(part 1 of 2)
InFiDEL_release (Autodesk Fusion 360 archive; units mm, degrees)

design "assAll" references "filaSens"
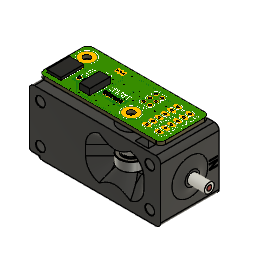
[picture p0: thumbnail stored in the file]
base_feature "Base Feature1"
base_feature "Base Feature1"
base_feature "Base Feature1"
base_feature "Base Feature1"
base_feature "Base Feature1"
base_feature "Base Feature1"
revolve "Revolve1" sketch "unnamed" AlongAngle 360
sketch "MainSketch" plane through (0, 0, 0) normal (0, 0, 1) x axis (1, 0, 0)
  line L1 (33.1, 16.4) -> (33.1, 4.8)
  line L2 (20.6, 11.4) -> (45.6, 11.4)
  line L3 (20.6, 9.8) -> (20.6, 11.4)
  line L4 (45.6, 9.8) -> (20.6, 9.8)
  line L5 (45.6, 11.4) -> (45.6, 9.8)
  line L6 (20.6, 9.8) -> (45.6, 11.4)
  line L7 (45.6, 9.8) -> (20.6, 11.4)
  line L8 (-2, -2) -> (-2, 22)
  line L9 (-2, 10.8604) -> (-2, -2)
  line L10 (-2, 19.7396) -> (-2, 10.8604)
  line L11 (-2, 22) -> (-2, 19.7396)
  line L12 (-2, 9.8969) -> (-2, 10.0463)
  line L13 (-2, 14.9334) -> (-2, 5.472)
  line L14 (52, -2) -> (52, 22)
  line L15 (52, 22) -> (52, -2)
  line L16 (52, 16.8544) -> (52, 14.8608)
  line L17 (52, 14.8608) -> (52, 16.8544)
  line L18 (52, 18.509) -> (52, 18.7911)
  line L19 (52, 17.416) -> (52, 18.509)
  line L20 (52, 16.3266) -> (52, 17.416)
  line L21 (52, 15.8861) -> (52, 16.3266)
  line L22 (52, 16.1522) -> (52, 15.8861)
  line L23 (52, 16.7975) -> (52, 16.1522)
  line L24 (52, 16.3987) -> (52, 16.7975)
  line L25 (52, 16.6738) -> (52, 16.3987)
  line L26 (52, 17.4116) -> (52, 16.6738)
  line L27 (52, 18.0675) -> (52, 17.4116)
  line L28 (52, 18.2785) -> (52, 18.0675)
  line L29 (52, 18.1646) -> (52, 18.2785)
  line L30 (52, 20.5) -> (52, 18.1646)
  line L31 (52, 19.9873) -> (52, 20.5)
  line L32 (52, 18.7671) -> (52, 19.9873)
  line L33 (52, 18.7911) -> (52, 18.7671)
  line L34 (52, -0.5) -> (52, 4.5)
  line L35 (52, 3.9729) -> (52, -0.5)
  line L36 (52, -0.5) -> (52, 3.9729)
  line L37 (52, 4.5) -> (52, -0.5)
  line L38 (52, 0.4167) -> (52, 4.5)
  line L39 (52, 4.5) -> (52, 0.4167)
  line L40 (52, -0.5) -> (52, 0.0063)
  line L41 (52, 0.0063) -> (52, -0.5)
  line L42 (52, 3.9937) -> (52, 0.0063)
  line L43 (52, 4.5) -> (52, 3.9937)
  line L44 (52, 3.9937) -> (52, 4.5)
  line L45 (52, 0.0063) -> (52, 3.9937)
  line L46 (52, 19.8165) -> (52, 20.5)
  line L47 (52, 16) -> (52, 19.8165)
  line L48 (52, 19.9873) -> (52, 16)
  line L49 (52, 20.5) -> (52, 19.9873)
  line L50 (52, 16) -> (52, 16.4557)
  line L51 (52, 16.4557) -> (52, 16)
  line L52 (52, 19.4747) -> (52, 16.4557)
  line L53 (52, 19.8734) -> (52, 19.4747)
  line L54 (52, 19.9971) -> (52, 19.8734)
  line L55 (52, 20.5) -> (52, 19.9971)
  line L56 (52, 16.4557) -> (52, 20.5)
  line L57 (52, 13.4092) -> (52, 7.0169)
  line L58 (52, 10.1345) -> (52, 7.0169)
  line L59 (20.6, 10.6) -> (45.6, 10.6)
  line L60 (-10, 8.5396) -> (-2, 8.5396)
  line L61 (60, 10.0041) -> (52, 10.0041)
  circle C1 centre (33.1, 16.4) radius 1.45
  circle C2 centre (33.1, 16.4) radius 5
  circle C3 centre (33.1, 4.8) radius 5
  circle C4 centre (33.103, 16) radius 1.4
  arc A1 centre (-2, 158.5396) radius 150 clockwise from (15.5501, 9.5698) to (-2, 8.5396)
  arc A2 centre (33.1, -139.4) radius 150 clockwise from (-2, 6.4355) to (15.5501, 9.5698)
  arc A3 centre (52, 160.0041) radius 150 clockwise from (52, 10.0041) to (42.55, 10.302)
  arc A4 centre (33.1, -139.4) radius 150 clockwise from (45.6, 10.0783) to (52, 9.4045)
  arc A5 centre (33.1, -139.4) radius 150 clockwise from (15.5501, 9.5698) to (42.55, 10.302)
  arc A6 centre (33.1, -139.4) radius 150 clockwise from (42.55, 10.302) to (45.6, 10.0783)
  point P2 (33.1, 4.8)
  point P3 (33.1, 4.8)
  point P4 (33.1, 16.4)
  point P5 (33.1, 16.4)
  point P6 (33.1, 16.4)
  point P11 (33.1, 10.6)
  point P14 (52, 9.4045)
  point P15 (-2, 6.4355)
  point P60 (45.6, 10.6)
  point P61 (20.6, 10.6)
  point P63 (-2, 8.5396)
  point P68 (52, 10.0041)
  point P67 (42.55, 10.302)
  point P71 (45.6, 10.0783)
  point P8 (20.6, 11.4)
  point P9 (20.6, 9.8)
  point P10 (45.6, 9.8)
  point P65 (-10, 8.5396)
  point P70 (60, 10.0041)
  coincident P2 P3
  vertical L1
  coincident P4 P5
  coincident P4 P6
  horizontal L2
  perpendicular L2 L3
  parallel L2 L4
  parallel L3 L5
  coincident L6 P11
  coincident L7 P11
  coincident L1 P11
  tangent C2 L2
  tangent L4 C3
  coincident P11 A4
  coincident P14 L14
  coincident P15 L13
  midpoint L5 P60
  midpoint L3 P61
  tangent L59 A4
  tangent A1 A4
  coincident L8 P63
  horizontal L60
  tangent A1 L60
  concentric A2 A4
  tangent A3 A4
  coincident L15 P68
  coincident P67 A4
  perpendicular L15 L61
  tangent A3 L61
  coincident L5 P71
  concentric A4 A5
  concentric A4 A6
  dimension "d29" diameter C2 = 10
  dimension "d30" distance P8 P9 = 1.6 (= "RollerCenter")
  dimension "d31" distance P9 P10 = 25
  dimension "d52" radius A4 = 150 (= "TensionArc")
  dimension "d54" radius A1 = 150 (= "TensionArc")
  dimension "d79" radius A3 = 150 (= "TensionArc")
  dimension "d80" distance P63 P65 = 8
  dimension "d81" distance P68 P70 = 8
  dimension "d318" diameter C1 = 2.9 (= "PinPressDia")
work_plane "WorkPlane1" AlongDistance 16.4
sketch "Sketch1" plane through (0, 16.4, 0) normal (0, 1, 0) x axis (1, 0, 0)
  line L1 (33.103, 13) -> (33.103, 0)
  line L2 (30.603, -2) -> (35.603, -2)
  line L3 (24.603, -8) -> (30.603, -2)
  line L4 (47.35, -8) -> (32.35, -8)
  line L5 (33.103, -8) -> (24.603, -8)
  line L6 (33.103, -8) -> (33.103, 0)
  line L7 (29.603, -3) -> (29.603, -8)
  point P2 (33.103, 0)
  point P3 (33.103, 0)
  point P6 (30.603, -2)
  point P7 (30.603, -2)
  point P11 (33.103, -8)
  point P12 (33.103, -8)
  point P13 (29.603, -8)
  point P14 (29.603, -3)
  coincident P2 P3
  vertical L1
  coincident P6 P7
  coincident L4 P11
  coincident L4 P12
  perpendicular L4 L6
  coincident P11 P12
  horizontal L5
  coincident L5 P13
  coincident L3 P14
  perpendicular L5 L7
  dimension "d2" angle L2 L3 = 135
  dimension "d3" distance P7 L7 = 1
revolve "Revolve2" sketch "Sketch1" AlongAngle 360
extrude "Extrude2" sketch "unnamed" blind 17
extrude "Extrude3" cut sketch "MainSketch" profile of C1 C4 along normal blind 21.8
sketch "Sketch2" plane through (0, 0, 0) normal (0, 0, -1) x axis (1, 0, 0)
  arc A1 centre (39.85, -15.8) radius 7.5 clockwise from (32.3789, -15.142) to (32.6121, -17.7655)
  circle C1 centre (39.85, -15.8) radius 3
  circle C2 centre (33.1, -16.4) radius 6
  arc A2 centre (33.1, -16.4) radius 1.45 clockwise from (32.3789, -15.142) to (32.6121, -17.7655)
  point P5 (33.1, -16.4)
  point P6 (33.1, -16.4)
  coincident P5 P6
  dimension "d13" diameter C2 = 12
sketch "Sketch3" plane through (0, 0, 0) normal (0, 0, 1) x axis (1, 0, 0)
  line L1 (14.76, 16.21) -> (18.26, 16.21)
  line L2 (16.51, 21.21) -> (16.51, 16.21)
  line L3 (16.51, 23.21) -> (16.51, 21.21)
  line L4 (20.01, 23.21) -> (16.51, 23.21)
  line L5 (20.01, 21.21) -> (20.01, 23.21)
  line L6 (16.51, 21.21) -> (20.01, 21.21)
  line L7 (11.01, 24.7652) -> (40.2281, 23.2905)
  line L8 (11.01, 24.21) -> (22.01, 24.21)
  line L9 (11.01, 20.21) -> (11.01, 24.21)
  line L10 (22.01, 20.21) -> (11.01, 20.21)
  line L11 (22.01, 24.21) -> (22.01, 20.21)
  line L12 (11.01, 20.21) -> (22.01, 24.21)
  line L13 (22.01, 20.21) -> (11.01, 24.21)
  line L14 (13.01, 23.21) -> (16.51, 23.21)
  line L15 (13.01, 21.21) -> (13.01, 23.21)
  line L16 (16.51, 21.21) -> (13.01, 21.21)
  line L17 (16.51, 23.21) -> (16.51, 21.21)
  line L18 (11.01, 24.21) -> (11.01, 24.7652)
  line L19 (22.01, 21.21) -> (20.01, 21.21)
  line L20 (11.01, 21.21) -> (13.01, 21.21)
  line L21 (34.0875, 20.6004) -> (22.01, 21.21)
  line L22 (43.3307, 23.1339) -> (40.2281, 23.2905)
  line L23 (45.4139, 20.8292) -> (43.3307, 23.1339)
  arc A1 centre (39.85, 15.8) radius 7.5 clockwise from (32.6121, 17.7655) to (32.3789, 15.142)
  arc A2 centre (39.85, 15.8) radius 7.5 clockwise from (32.5804, 13.9552) to (32.3789, 15.142)
  arc A3 centre (39.85, 15.8) radius 7.5 clockwise from (32.6121, 17.7655) to (33.02, 18.8986)
  point P4 (16.51, 16.21)
  point P12 (40.2281, 23.2905)
  point P18 (16.51, 22.21)
  point P14 (22.01, 24.21)
  point P21 (22.01, 21.21)
  point P22 (11.01, 21.21)
  point P26 (45.4139, 20.8292)
  point P5 (16.51, 21.21)
  point P6 (16.51, 23.21)
  point P7 (20.01, 23.21)
  midpoint L1 P4
  perpendicular L1 L2
  parallel L2 L3
  perpendicular L3 L4
  perpendicular L4 L5
  horizontal L6
  coincident A1 P12
  tangent A1 L7
  horizontal L8
  perpendicular L8 L9
  parallel L8 L10
  parallel L9 L11
  coincident L12 P18
  coincident L13 P18
  midpoint L3 P18
  horizontal L14
  vertical L15
  horizontal L16
  vertical L17
  equal L4 L14
  vertical L18
  coincident L7 P14
  coincident L11 P21
  perpendicular L11 L19
  coincident L9 P22
  perpendicular L9 L20
  parallel L7 L21
  tangent A1 L22
  coincident A1 P26
  tangent A1 L23
  dimension "d16" distance P4 P5 = 5
  dimension "d17" distance P5 P6 = 2
  dimension "d18" distance P6 P7 = 3.5
  dimension "d19" distance L5 L11 = 2
  dimension "d20" distance L4 L8 = 1
  dimension "d24" angle L22 L23 = 135
extrude "Extrude5" add sketch "Sketch3" profile of L3 L4 L5 L6 A1 L7 L8 L9 L11 L14 L15 L16 L17 L18 L19 L20 L21 L22 L23 to an object User Parameter 5 named "MagnetOffset" User Parameter 5 named "Pretension" User Parameter 1.6 named "RollerCenter" User Parameter 150 named "TensionArc" User Parameter 2.9 named "PinPressDia" User Parameter 4.15 named "PTFEclear" User Parameter 3.7 named "M3InsertDia" User Parameter 1.4 named "Roller_Center_dyn"
revolve "Revolve3" sketch "Sketch3" AlongAngle 360
sketch "Sketch5" plane through (0, 0, 8) normal (0, 0, 1) x axis (-1, 0, 0)
  line L1 (-43.3307, -23.1339) -> (-45.4139, -20.8292)
  line L2 (-40.2281, -23.2905) -> (-43.3307, -23.1339)
  line L3 (-11.01, -24.7652) -> (-40.2281, -23.2905)
  line L4 (-11.01, -21.21) -> (-11.01, -24.7652)
  line L5 (-22.01, -21.21) -> (-11.01, -21.21)
  line L6 (-34.0875, -20.6004) -> (-22.01, -21.21)
  line L7 (-13.01, -21.21) -> (-20.01, -21.21)
  line L8 (-16.51, -21.21) -> (-33.103, -16.4)
  circle C1 centre (-33.1, -16.4) radius 1.45
  circle C2 centre (-39.85, -15.8) radius 5
  arc A1 centre (-39.85, -15.8) radius 7.5 clockwise from (-45.4139, -20.8292) to (-32.9316, -12.9042)
  arc A2 centre (-39.85, -15.8) radius 7.5 clockwise from (-33.5512, -19.8712) to (-34.0875, -20.6004)
  arc A3 centre (-33.103, -16.4) radius 3.5 clockwise from (-32.9316, -12.9042) to (-33.5512, -19.8712)
  point P13 (-33.103, -16.4)
  point P16 (-33.103, -16.4)
  coincident P13 P16
extrude "Extrude6" add sketch "Sketch5" profile of L5 L6 A2 A3 L7 L8 against normal blind 5
extrude "Extrude7" cut of existing geometry blind -1.4
fillet "Fillet1" radius 2
sketch "Sketch6" plane through (1.2748, 25.2566, 0) normal (0.0504, 0.9987, 0) x axis (-0.9987, 0.0504, 0)
  line L1 (-39.0029, 8) -> (-9.7476, 8)
  line L2 (-39.0029, 0) -> (-39.0029, 8)
  line L3 (-9.7476, 0) -> (-39.0029, 0)
  line L4 (-9.7476, 8) -> (-9.7476, 0)
  line L5 (-14.3324, 5.4833) -> (-28.319, 8)
  circle C1 centre (-15.319, 0) radius 5.5714
  closed curve K1 centre (-15.319, 0)
  point P5 (-9.7476, 0)
  point P10 (-28.319, 8)
  point P11 (-14.3324, 5.4833)
  point P6 (-15.319, 0)
  concentric C1 K1
  coincident P5 C1
  coincident L1 P10
  coincident C1 P11
  tangent C1 L5
  dimension "d39" distance P6 P10 = 13
extrude "Extrude8" cut sketch "Sketch6" profile of L1 L4 C1 L5 against normal blind 14
fillet "Fillet2" radius 20
fillet "Fillet3" radius 5
extrude "Extrude9" cut sketch "Sketch2" to an object
fillet "Fillet4" radius 5
split "Split1" bodies "LeverPlastic"
sketch "Sketch7" plane through (0, 16.4, 0) normal (0, 1, 0) x axis (1, 0, 0)
  line L1 (31.65, -8) -> (31.65, -2)
  line L2 (29.603, -8) -> (31.65, -8)
  line L3 (29.603, -7.9999) -> (29.603, -8)
  line L4 (29.1901, -3) -> (29.1901, -7.9807)
  line L5 (29.603, -3) -> (29.1901, -3)
  line L6 (30.603, -2) -> (29.603, -3)
  line L7 (31.65, -2) -> (30.603, -2)
  line L8 (26.5009, -3) -> (29.1901, -3)
  line L9 (27.1, -3) -> (29.1901, -3)
  line L10 (27.1, 2.2) -> (27.1, -3)
  line L11 (33.1, 2.2) -> (27.1, 2.2)
  line L12 (33.8821, -2) -> (33.02, -2)
  line L13 (33.1, -2) -> (33.1, 2.2)
  line L14 (33.1, -2) -> (31.65, -2)
  line L15 (34.55, -8) -> (31.65, -8)
  line L16 (34.55, -8) -> (34.55, -2)
  line L17 (33.1, 3.5) -> (33.1, -8)
  closed curve K1 centre (29.6296, -3)
  point P8 (29.1901, -3)
  point P13 (29.1901, -3)
  point P19 (33.1, -2)
  point P2 (31.65, -2)
  point P20 (31.65, -2)
  point P3 (31.65, -8)
  point P21 (31.65, -8)
  point P22 (34.55, -8)
  point P25 (33.1, -8)
  point P15 (27.1, 2.2)
  point P16 (33.1, 2.2)
  coincident P8 P13
  parallel L5 L9
  perpendicular L5 L10
  perpendicular L10 L11
  coincident L12 P19
  perpendicular L11 L13
  coincident P2 P20
  coincident P3 P21
  perpendicular L1 L15
  coincident P22 L16
  midpoint L15 P25
  perpendicular L15 L17
  collinear L13 L17
  dimension "d50" distance P15 P16 = 6 (= "( ( 10 + 2 ) / 2 ) * 1 mm")
revolve "Revolve4" sketch "Sketch7" AlongAngle 360
combine "Combine1"
work_plane "WorkPlane2" AlongDistance 33.1
sketch "Sketch8" plane through (33.1, 0, 0) normal (1, 0, 0) x axis (0, 1, 0)
  circle C1 centre (10.6, 0) radius 4
  point P2 (10.6, 0)
  point P3 (10.6, 0)
  coincident P2 P3
  dimension "d56" diameter C1 = 8
sweep "Sweep1" sketch "Sketch8" TwistAngle 0 TaperAngle 0
fillet "Fillet5" radius 0.5
sketch "Sketch9" plane through (0, 0, 3) normal (0, 0, -1) x axis (1, 0, 0)
  line L1 (23.715, -19.1214) -> (26.5009, -18.3138)
  line L2 (27.656, -18.9225) -> (23.715, -19.1214)
  curve K1 (34.5946, -13.2384) -> (38.1514, -13.1621)
  line L3 (31.6015, -13.2384) -> (31.6054, -13.2384)
  arc A1 centre (33.103, -16.4) radius 3.5 clockwise from (29.8112, -15.2106) to (31.6015, -13.2384)
  arc A2 centre (25.1088, -13.5115) radius 5 clockwise from (29.8112, -15.2106) to (26.5009, -18.3138)
  arc A3 centre (33.1, -16.4) radius 6 clockwise from (38.6944, -18.5685) to (27.656, -18.9225)
  arc A4 centre (39.85, -15.8) radius 3 clockwise from (38.6944, -18.5685) to (38.2242, -13.2787)
  arc A5 centre (33.1, -16.4) radius 6 clockwise from (38.1514, -13.1621) to (38.2242, -13.2787)
  arc A6 centre (33.1, -16.4) radius 3.497 clockwise from (34.5946, -13.2384) to (31.6054, -13.2384)
  circle C1 centre (38.1643, -13.054) radius 1.1892
extrude "Extrude10" cut sketch "Sketch9" profile of A4 A5 C1 along normal blind 0.9
fillet "Fillet6" radius 0.8
mirror "Mirror1" mirrorStitchTolerance 0.1
component_from_bodies "Body->Comp1"
base_feature "Base Feature1"
position "Position1"
joint "Assemble1" alignAngle 0 alignOffsetX 0 alignOffsetY 0 alignOffsetZ 0
copy_paste "CopyPaste1"
copy_paste "CopyPaste2"
joint "Assemble2" alignAngle 0 alignOffsetX 0 alignOffsetY 0 alignOffsetZ 0
as_built_joint "As-built1"
copy_paste "CutPaste1"
copy_paste "CutPaste2"
copy_paste "CutPaste3"
work_plane "WorkPlane3" AlongDistance 52
sketch "PTFE/Guide/Filament Profiles" plane through (52, 0, 0) normal (1, 0, 0) x axis (0, 1, 0)
  line L1 (-6.311, 3) -> (10.0041, 3)
  line L2 (-6.311, -3) -> (-6.311, 3)
  line L3 (10.0041, -3) -> (-6.311, -3)
  circle C1 centre (10.0041, 0) radius 1
  circle C2 centre (10.0041, 0) radius 2
  circle C3 centre (10.0041, 0) radius 3
  point P2 (10.0041, 0)
  point P3 (10.0041, 0)
  point P4 (10.0041, 0)
  point P6 (10.0041, 3)
  point P9 (10.0041, -3)
  coincident P2 P3
  coincident P3 P4
  concentric C1 C3
  coincident C3 P6
  horizontal L1
  perpendicular L1 L2
  perpendicular L2 L3
  coincident C3 P9
  tangent C3 L3
  tangent C3 L1
  dimension "d85" diameter C1 = 2
  dimension "d86" diameter C2 = 4
  dimension "d87" diameter C3 = 6
sweep "Sweep2" sketch "PTFE/Guide/Filament Profiles" TwistAngle 0 TaperAngle 0 bodies "Filament"
sweep "Sweep3" sketch "PTFE/Guide/Filament Profiles" TwistAngle 0 TaperAngle 0 bodies "PTFE"
sweep "Sweep4" sketch "PTFE/Guide/Filament Profiles" TwistAngle 0 TaperAngle 0 bodies "PTFEGuide"
sketch "Sketch11" plane through (0, 0, 0) normal (0, 0, 1) x axis (1, 0, 0)
  circle C1 centre (33.1, 16.4) radius 5
  circle C2 centre (33.1, 4.8) radius 5
  circle C3 centre (33.1, 4.8) radius 6
  circle C4 centre (33.1, 16.4) radius 6
  dimension "d112" = 1
  dimension "d113" = 1
extrude "Extrude11" cut sketch "Sketch11" distance 6 bodies "PTFEGuide (1)"
sketch "Sketch12" plane through (0, 0, 0) normal (0, 0, 1) x axis (1, 0, 0)
  line L1 (39.1, 15.6) -> (27.1, 15.6)
  line L2 (39.1, 5.6) -> (39.1, 15.6)
  line L3 (27.1, 5.6) -> (39.1, 5.6)
  line L4 (27.1, 15.6) -> (27.1, 5.6)
  line L5 (39.1, 5.6) -> (27.1, 15.6)
  line L6 (27.1, 5.6) -> (39.1, 15.6)
  point P6 (33.1, 10.6)
  point P7 (33.1, 10.6)
  point P4 (39.1, 5.6)
  point P5 (27.1, 5.6)
  point P3 (39.1, 15.6)
  horizontal L1
  perpendicular L1 L2
  parallel L1 L3
  parallel L2 L4
  coincident L5 P6
  coincident L6 P6
  coincident P6 P7
  dimension "d116" distance P4 P5 = 12
  dimension "d117" distance P3 P4 = 10
extrude "Extrude12" cut sketch "Sketch12" profile of L1 L2 L3 L4 distance 5 bodies "PTFE (1)"
combine "Combine2"
combine "Combine3"
combine "Combine4"
combine "Combine5"
combine "Combine6"
combine "Combine7"
sketch "Sketch13" plane through (0, 0, 0) normal (0, 0, 1) x axis (1, 0, 0)
  line L1 (30.1, 5.6) -> (36.1, 5.6)
  line L2 (30.1, 15.6) -> (30.1, 5.6)
  line L3 (36.1, 15.6) -> (30.1, 15.6)
  line L4 (36.1, 5.6) -> (36.1, 15.6)
  line L5 (30.1, 15.6) -> (36.1, 5.6)
  line L6 (36.1, 15.6) -> (30.1, 5.6)
  point P6 (33.1, 10.6)
  point P7 (33.1, 10.6)
  point P4 (30.1, 15.6)
  point P5 (36.1, 15.6)
  point P2 (36.1, 5.6)
  horizontal L1
  perpendicular L1 L2
  parallel L1 L3
  parallel L2 L4
  coincident L5 P6
  coincident L6 P6
  coincident P6 P7
  dimension "d120" distance P4 P5 = 6
  dimension "d121" distance P2 P5 = 10
extrude "Extrude13" cut sketch "Sketch13" profile of L1 L2 L3 L4 distance 7.5
chamfer "Chamfer1" distance 1
fillet "Fillet7" radius 1
sketch "BlockMain" plane through (0, 0, 0) normal (0, 0, 1) x axis (1, 0, 0)
  line L1 (52, -2) -> (-2, 22)
  line L2 (52, 22) -> (-2, 22)
  line L3 (52, -2) -> (52, 22)
  line L4 (-2, -2) -> (52, -2)
  line L5 (-2, 22) -> (-2, -2)
  line L6 (52, -2) -> (-2, 22)
  line L7 (-2, -2) -> (52, 22)
  curve K1 (33.4365, 6.159) -> (32.5467, 6.086)
  curve K2 (34.3171, 5.4919) -> (33.4365, 6.159)
  circle C1 centre (4.3, 15.3) radius 1.4
  circle C2 centre (4.3, 15.3) radius 1.4
  arc A1 centre (33.1, 4.8) radius 1.4 clockwise from (34.3171, 5.4919) to (32.5467, 6.086)
  circle C3 centre (33.1, 4.8) radius 1.4
  circle C4 centre (39.85, 15.8) radius 1.4
  circle C5 centre (39.85, 15.8) radius 1.4
  point P2 (-2, 22)
  point P4 (-2, 22)
  point P3 (52, -2)
  point P5 (52, -2)
  point P6 (-2, 22)
  point P10 (25, 10)
  coincident P2 P4
  coincident P3 P5
  horizontal L2
  perpendicular L2 L3
  parallel L2 L4
  parallel L3 L5
  coincident P2 P6
  coincident L6 P10
  coincident L7 P10
  midpoint L1 P10
sketch "Sketch15" plane through (0, 0, 0) normal (0, 0, 1) x axis (1, 0, 0)
  line L1 (42.2008, 23.1909) -> (44.8204, 20.2928)
  line L2 (40.2281, 23.2905) -> (42.2008, 23.1909)
  line L3 (30.0035, 23.8065) -> (40.2281, 23.2905)
  line L4 (29.665, 17.1005) -> (30.0035, 23.8065)
  line L5 (26.5821, 19.0893) -> (19.3193, 21.1947)
  line L6 (29.1192, 23.8512) -> (28.8166, 17.8572)
  line L7 (15.5889, 24.5341) -> (29.1192, 23.8512)
  line L8 (15.4574, 21.9275) -> (15.5889, 24.5341)
  curve K1 (28.8166, 17.8572) -> (29.665, 17.1005)
  line L9 (30.0035, 23.8065) -> (29.665, 17.1005)
  line L10 (30.0035, 23.8065) -> (29.1192, 23.8512)
  line L11 (28.8166, 17.8572) -> (29.1192, 23.8512)
  line L12 (13.2048, 22.0335) -> (11.01, 22.0493)
  curve K2 (13.2048, 22.0335) -> (15.4574, 21.9275)
  line L13 (15.5889, 24.5341) -> (15.4574, 21.9275)
  line L14 (11.01, 24.7652) -> (15.5889, 24.5341)
  line L15 (11.01, 22.0493) -> (11.01, 24.7652)
  line L16 (27.625, 16.3591) -> (28.1068, 25.9048)
  line L17 (43.129, 25.1466) -> (46.3041, 21.6339)
  line L18 (40.3289, 25.2879) -> (43.129, 25.1466)
  line L19 (28.1068, 25.9048) -> (40.3289, 25.2879)
  line L20 (14.4092, 20.9975) -> (14.6406, 25.5832)
  line L21 (14.6406, 25.5832) -> (30.1683, 24.7995)
  line L22 (30.1683, 24.7995) -> (29.6517, 14.5656)
  line L23 (26.3037, 18.1289) -> (19.0409, 20.2342)
  line L24 (13.3584, 20.0164) -> (13.6923, 26.6324)
  line L25 (13.6923, 26.6324) -> (31.2174, 25.7478)
  line L26 (31.2174, 25.7478) -> (30.8141, 17.7564)
  line L27 (26.0253, 17.1684) -> (18.7624, 19.2738)
  line L28 (28.6463, 16.7559) -> (29.0552, 24.8557)
  line L29 (29.0552, 24.8557) -> (40.2785, 24.2892)
  line L30 (40.2785, 24.2892) -> (42.6649, 24.1687)
  line L31 (42.6649, 24.1687) -> (45.5623, 20.9633)
  curve K3 (13.1975, 21.0335) -> (16.4038, 20.8413)
  line L32 (13.1975, 21.0335) -> (10.01, 21.0565)
  line L33 (10.01, 21.0565) -> (10.01, 25.817)
  line L34 (10.01, 25.817) -> (16.6381, 25.4824)
  line L35 (16.6381, 25.4824) -> (16.4038, 20.8413)
  curve K4 (13.1903, 20.0335) -> (17.3503, 19.7552)
  line L36 (13.1903, 20.0335) -> (9.01, 20.0637)
  line L37 (9.01, 20.0637) -> (9.01, 26.8687)
  line L38 (9.01, 26.8687) -> (17.6872, 26.4307)
  line L39 (17.6872, 26.4307) -> (17.3503, 19.7552)
  line L40 (10.0028, 20.0566) -> (10.01, 21.0565)
  line L41 (44.0773, 24.0975) -> (42.6649, 24.1687)
  arc A1 centre (25.1088, 13.5115) radius 5.8 clockwise from (29.665, 17.1005) to (30.5636, 15.4825)
  arc A2 centre (33.103, 16.4) radius 2.7 clockwise from (31.987, 13.9414) to (30.5636, 15.4825)
  arc A3 centre (29.5899, 8.66) radius 5.8 clockwise from (31.987, 13.9414) to (34.3506, 11.9729)
  arc A4 centre (39.85, 15.8) radius 6.7 clockwise from (44.8204, 20.2928) to (34.3506, 11.9729)
  circle C1 centre (33.1, 16.4) radius 1.45
  circle C2 centre (39.85, 15.8) radius 5
  arc A5 centre (13.5282, 1.2171) radius 20.8 clockwise from (15.4574, 21.9275) to (19.3193, 21.1947)
  arc A6 centre (24.9673, 13.5187) radius 5.8 clockwise from (26.5821, 19.0893) to (28.8166, 17.8572)
  arc A7 centre (25.1088, 13.5115) radius 3.8 clockwise from (27.625, 16.3591) to (28.6827, 14.8028)
  arc A8 centre (33.103, 16.4) radius 4.7 clockwise from (31.1604, 12.1202) to (28.6827, 14.8028)
  arc A9 centre (29.5899, 8.66) radius 3.8 clockwise from (31.1604, 12.1202) to (32.709, 10.8305)
  arc A10 centre (39.85, 15.8) radius 8.7 clockwise from (46.3041, 21.6339) to (32.709, 10.8305)
  arc A11 centre (13.5282, 1.2171) radius 19.8 clockwise from (14.4092, 20.9975) to (19.0409, 20.2342)
  arc A12 centre (24.9673, 13.5187) radius 4.8 clockwise from (26.3037, 18.1289) to (29.6517, 14.5656)
  arc A13 centre (13.5282, 1.2171) radius 18.8 clockwise from (13.3584, 20.0164) to (18.7624, 19.2738)
  arc A14 centre (28.8166, 17.8572) radius 2 clockwise from (30.8141, 17.7564) to (27.4893, 16.3611)
  arc A15 centre (24.9673, 13.5187) radius 3.8 clockwise from (26.0253, 17.1684) to (27.4893, 16.3611)
  arc A16 centre (25.1088, 13.5115) radius 4.8 clockwise from (28.6463, 16.7559) to (29.6231, 15.1427)
  arc A17 centre (39.85, 15.8) radius 7.7 clockwise from (45.5623, 20.9633) to (33.5298, 11.4017)
  arc A18 centre (29.5899, 8.66) radius 4.8 clockwise from (31.5737, 13.0308) to (33.5298, 11.4017)
  arc A19 centre (33.103, 16.4) radius 3.7 clockwise from (31.5737, 13.0308) to (29.6231, 15.1427)
  point P84 (10.0028, 20.0566)
  point P85 (44.0773, 24.0975)
  coincident L36 P84
  perpendicular L36 L40
  coincident L17 P85
  parallel L30 L41
  dimension "d127" = 2
  dimension "d128" = 1
  dimension "d129" = 2
  dimension "d130" = 1
  dimension "d131" = 1
  dimension "d132" = 2
extrude "Extrude14" new body sketch "Sketch15" profile of L1 L2 L3 L4 A1 A2 A3 A4 C1 C2 A5 L5 A6 L6 L7 L8 K1 L9 L10 L11 L12 K2 L13 L14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 distance 9 bodies "LeverClearance"
sketch "Sketch16" plane through (0, 0, 0) normal (0, 0, 1) x axis (1, 0, 0)
sketch "Sketch17" plane through (0, 0, 0) normal (0, 0, 1) x axis (1, 0, 0)
  circle C1 centre (33.1, 16.4) radius 5
  circle C2 centre (33.1, 16.4) radius 6
  dimension "d136" = 1
extrude "Extrude15" new body sketch "MainSketch" + "Sketch17" profile of S1:C1 S1:C2 S1:C4 S2:C1 S2:C2 distance 6 bodies "BlockClearance"
combine "Combine8" bodies "LeverClearance"
move "Move1" RotateAngle 5
sketch "Sketch18" plane through (0, 22, 0) normal (0, 1, 0) x axis (-1, 0, 0)
  line L1 (-10.1856, 12.5) -> (-2, 12.5)
  line L2 (-11.3403, 3.9309) -> (-11.3403, 11.5)
  line L3 (-10.01, -0.1634) -> (-10.01, 0.1634)
  line L4 (-19.3211, -7.2622) -> (-14.4571, -5.9589)
  line L5 (-46.35, -9) -> (-32.5208, -9)
  line L6 (-48.35, 7) -> (-48.35, -7)
  line L7 (-32.5208, 9) -> (-46.35, 9)
  line L8 (-21.6797, 11.5) -> (-21.6797, 7.8344)
  line L9 (-48, 12.5) -> (-22.8344, 12.5)
  line L10 (-52, -8.5) -> (-52, 8.5)
  line L11 (-2, -12.5) -> (-48, -12.5)
  line L12 (2, 8.5) -> (2, -8.5)
  line L13 (2, 12.5) -> (-52, 12.5)
  line L14 (2, -12.5) -> (2, 12.5)
  line L15 (-52, -12.5) -> (2, -12.5)
  line L16 (-52, 12.5) -> (-52, -12.5)
  line L17 (2, -12.5) -> (-52, 12.5)
  line L18 (-52, -12.5) -> (2, 12.5)
  line L19 (2, 0) -> (-52, 0)
  closed curve K1 centre (-10.1856, 11.5)
  arc A1 centre (-16.01, 0.1634) radius 6 clockwise from (-11.3403, 3.9309) to (-10.01, 0.1634)
  arc A2 centre (-16.01, -0.1634) radius 6 clockwise from (-10.01, -0.1634) to (-14.4571, -5.9589)
  arc A3 centre (-32.5208, 42) radius 51 clockwise from (-19.3211, -7.2622) to (-32.5208, -9)
  arc A4 centre (-46.35, -7) radius 2 clockwise from (-46.35, -9) to (-48.35, -7)
  arc A5 centre (-46.35, 7) radius 2 clockwise from (-48.35, 7) to (-46.35, 9)
  arc A6 centre (-32.5208, -42) radius 51 clockwise from (-32.5208, 9) to (-21.6797, 7.8344)
  closed curve K2 centre (-22.8344, 11.5)
  arc A7 centre (-48, 8.5) radius 4 clockwise from (-52, 8.5) to (-48, 12.5)
  arc A8 centre (-48, -8.5) radius 4 clockwise from (-48, -12.5) to (-52, -8.5)
  arc A9 centre (-2, -8.5) radius 4 clockwise from (2, -8.5) to (-2, -12.5)
  arc A10 centre (-2, 8.5) radius 4 clockwise from (-2, 12.5) to (2, 8.5)
  point P42 (-25, 0)
  point P43 (0, 0)
  point P44 (-52, 0)
  point P45 (-52, 0)
  point P46 (2, 0)
  point P47 (-52, 0)
  point P39 (2, 12.5)
  point P40 (2, -12.5)
  horizontal L13
  perpendicular L13 L14
  parallel L13 L15
  parallel L14 L16
  coincident L17 P42
  coincident L18 P42
  horizontal P42 P43
  coincident P44 P45
  midpoint L12 P46
  midpoint L16 P47
  midpoint L14 P46
  dimension "d140" distance P39 P40 = 25
extrude "Extrude16" new body sketch "Sketch18" profile of L1 K1 L2 A1 L3 A2 L4 A3 L5 A4 L6 A5 L7 A6 L8 K2 L9 A7 L10 A8 L11 A9 L12 A10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 against normal blind 24
sweep "Sweep6" sketch "PTFE/Guide/Filament Profiles" TwistAngle 0 TaperAngle 0
combine "Combine9"
sweep "Sweep5" sketch "PTFE/Guide/Filament Profiles" TwistAngle 0 TaperAngle 0
sketch "Sketch19" plane through (0, 0, 4) normal (0, 0, 1) x axis (-1, 0, 0)
  circle C1 centre (-39.85, -15.8) radius 3
  circle C2 centre (-39.85, -15.8) radius 5
  circle C3 centre (-39.85, -15.8) radius 5
work_plane "WorkPlane4" AlongDistance 15.8
sketch "Sketch20" plane through (0, 15.8, 0) normal (0, 1, 0) x axis (1, 0, 0)
  line L1 (34.85, -4) -> (44.85, -4)
  line L2 (44.85, -4.2) -> (34.85, -4.2)
  line L3 (39.85, -18) -> (39.85, -4)
  line L4 (44.85, -8) -> (34.85, -8)
  line L5 (48.55, -9) -> (33.1693, -9)
  line L6 (43.35, -9) -> (42.35, -8)
  point P12 (42.35, -8)
  point P13 (43.35, -9)
  perpendicular L2 L3
  coincident L4 P12
  coincident L5 P13
  dimension "d150" angle L4 L6 = 45
  dimension "d151" distance L3 P12 = 2.5
revolve "Revolve5" sketch "Sketch20" AlongAngle 360
sketch "Sketch21" plane through (0, 0, -12.5) normal (0, 0, -1) x axis (1, 0, 0)
  line L1 (52, -22) -> (-2, -22)
  line L2 (52, 2) -> (52, -22)
  line L3 (-2, 2) -> (52, 2)
  line L4 (-2, -22) -> (-2, 2)
sketch "Sketch22" plane through (0, 0, 0) normal (0, 0, 1) x axis (1, 0, 0)
  line L1 (27.1, 4.8) -> (33.1, 4.8)
  line L2 (39.1, 4.8) -> (33.1, 4.8)
  line L3 (27.1, -4.6) -> (27.1, 4.8)
  line L4 (39.1, -4.6) -> (27.1, -4.6)
  line L5 (39.1, 4.8) -> (39.1, -4.6)
  circle C1 centre (33.1, 4.8) radius 5
  circle C2 centre (33.1, 4.8) radius 6
  point P2 (33.1, 4.8)
  point P4 (33.1, 4.8)
  point P5 (27.1, 4.8)
  point P6 (39.1, 4.8)
  coincident P2 P4
  coincident C2 P5
  coincident C2 P6
  tangent C2 L3
  perpendicular L3 L4
  vertical L5
  dimension "d163" = 1
extrude "Extrude17" cut sketch "MainSketch" + "Sketch22" profile of S1:C3 S2:C1 S2:C2 S2:L1 S2:L2 S2:L3 S2:L4 S2:L5 distance 6
sketch "Sketch23" plane through (33.1, 0, 0) normal (1, 0, 0) x axis (0, 1, 0)
  line L1 (4.8, -9.7366) -> (4.8, 0)
  line L2 (2.3, -2) -> (4.8, -2)
  line L3 (4.8, -3) -> (-2, -3)
  line L4 (1.3, -3) -> (2.3, -2)
  point P2 (4.8, 0)
  point P4 (4.8, 0)
  point P5 (4.8, -2)
  point P9 (1.3, -3)
  point P6 (2.3, -2)
  vertical L1
  coincident P2 P4
  coincident L1 P5
  perpendicular L1 L2
  coincident L3 P9
  dimension "d166" distance P5 P6 = 2.5
  dimension "d167" angle L2 L4 = 45
  dimension "d168" distance L2 L3 = 1
revolve "Revolve6" sketch "Sketch23" AlongAngle 360
mirror "Mirror2" mirrorStitchTolerance 0.1
hole "Hole1" HoleDepth 24.5 HoleDiameter 2.9 (= "PinPressDia") TipAngle 180 CSDiameter 4 CSAngle 90
sketch "Sketch24" plane through (0, 0, 12.5) normal (0, 0, 1) x axis (-1, 0, 0)
  line L1 (2, -22) -> (-52, -22)
  line L2 (2, 2) -> (2, -22)
  line L3 (-52, 2) -> (2, 2)
  line L4 (-52, -22) -> (-52, 2)
  line L5 (-4.3, -15.3) -> (-33.1, -4.8)
  circle C1 centre (-4.3, -15.3) radius 1.4
  circle C2 centre (-33.1, -4.8) radius 1.4
  point P7 (-33.1, -4.8)
  point P8 (-33.1, -4.8)
  point P6 (-4.3, -15.3)
  point P9 (-4.3, -15.3)
  coincident P7 P8
  coincident P6 P9
work_plane "WorkPlane5" RotateAngle 90
sketch "Sketch25" plane through (18.7, 10.05, 12.5) normal (0.3425, 0.9395, 0) x axis (-0.9395, 0.3425, 0)
sketch "Sketch26" plane through (18.7, 10.05, 12.5) normal (0.3425, 0.9395, 0) x axis (-0.9395, 0.3425, 0)
  line L1 (-10.3272, 0) -> (-20.3272, 0)
  line L2 (-15.3272, 12.5669) -> (-15.3272, 0)
  line L3 (19.0087, 0) -> (10.3272, 0)
  line L4 (15.3272, 12.0764) -> (15.3272, 0)
  line L5 (-16.7272, 2) -> (-13.9272, 2)
  line L6 (-12.3272, 2) -> (-15.3272, 2)
  line L7 (-23.4343, 0) -> (0.209, 0)
  line L8 (-10.3272, 0) -> (-12.3272, 2)
  line L9 (12.3272, 2) -> (18.3272, 2)
  line L10 (18.3272, 2) -> (15.3272, 2)
  line L11 (15.3203, 0) -> (23.541, 0)
  line L12 (20.3272, 0) -> (18.3272, 2)
  point P16 (-10.3272, 0)
  point P23 (20.3272, 0)
  point P12 (-15.3272, 2)
  point P4 (-15.3272, 0)
  point P24 (-15.3272, 0)
  point P10 (-13.9272, 2)
  point P8 (15.3272, 0)
  point P25 (15.3272, 0)
  point P19 (15.3272, 2)
  point P13 (-12.3272, 2)
  point P20 (18.3272, 2)
  perpendicular L1 L2
  perpendicular L2 L6
  coincident L7 P16
  coincident L11 P23
  parallel L9 L10
  coincident L2 P12
  coincident P4 P24
  coincident P10 L6
  coincident P8 P25
  vertical L4
  coincident L4 P19
  coincident L9 P19
  dimension "d173" angle L6 L8 = 45
  dimension "d174" distance P12 P13 = 3
  dimension "d175" angle L10 L12 = 45
  dimension "d176" distance P19 P20 = 3
revolve "Revolve7" sketch "Sketch26" AlongAngle 360
revolve "Revolve8" sketch "Sketch26" AlongAngle 360
hole "Hole3" HoleDepth 16 HoleDiameter 3.7 (= "M3InsertDia") TipAngle 118 CSDiameter 4 CSAngle 90
hole "Hole4" HoleDepth 8 HoleDiameter 3.7 (= "M3InsertDia") TipAngle 118 CSDiameter 4 CSAngle 90
hole "Hole5" HoleDepth 14 HoleDiameter 3 TipAngle 118
fillet "Fillet8" radius 2
fillet "Fillet9" radius 8
sketch "Sketch27" plane through (0, 0, -9) normal (0, 0, 1) x axis (-1, 0, 0)
  line L1 (-25.9586, -15.9583) -> (-18.5399, -17.4227)
  line L2 (-17.3841, -22) -> (-45.9533, -22)
  line L3 (-17.635, -19.1331) -> (-17.3841, -22)
  line L4 (-48.55, -26.7232) -> (-48.55, -15.8)
  line L5 (-44.2, -26.5) -> (-48.55, -26.7232)
  line L6 (-45.7, -17.5) -> (-44.2, -26.5)
  line L7 (-48.55, -15.8) -> (-45.7, -17.5)
  arc A1 centre (-9.6654, -18.4358) radius 8 clockwise from (-17.635, -19.1331) to (-17.6196, -17.5807)
  arc A2 centre (-14.8993, 1.0215) radius 18.8 clockwise from (-17.6196, -17.5807) to (-18.5399, -17.4227)
  arc A3 centre (-25.2228, -12.2302) radius 3.8 clockwise from (-25.9586, -15.9583) to (-27.4874, -15.2817)
  arc A4 centre (-28.6793, -16.8877) radius 2 clockwise from (-27.94, -15.0294) to (-27.4874, -15.2817)
  arc A5 centre (-25.3643, -12.2355) radius 3.8 clockwise from (-27.94, -15.0294) to (-28.8121, -13.8333)
  arc A6 centre (-33.0763, -15.8097) radius 4.7 clockwise from (-31.5142, -11.3769) to (-28.8121, -13.8333)
  arc A7 centre (-30.2512, -7.7929) radius 3.8 clockwise from (-31.5142, -11.3769) to (-33.1693, -10.2271)
  arc A8 centre (-39.85, -15.8) radius 8.7 clockwise from (-45.9533, -22) to (-33.1693, -10.2271)
  circle C1 centre (-39.85, -15.8) radius 3.5
  point P21 (-48.55, -15.8)
  coincident A8 P21
  tangent A8 L4
  vertical L4
extrude "Extrude18" cut sketch "Sketch27" profile of A8 L2 L4 L5 L6 to an object
fillet "Fillet10" radius 1
combine "Combine10"
sketch "Sketch28" plane through (36.1, 0, 0) normal (-1, 0, 0) x axis (0, -1, 0)
  curve K1 (-11.2038, 0.7736) -> (-9.9962, 0.819)
  line L1 (-9.9962, 2.9446) -> (-9.9962, 0.819)
  curve K2 (-9.9962, 2.9446) -> (-10.57, 3)
  curve K3 (-10.57, 3) -> (-11.2038, 2.9323)
  line L2 (-11.2038, 0.7736) -> (-11.2038, 2.9323)
  line L3 (-12, -5.2) -> (-9.2, -5.2)
  line L4 (-12, 5.2) -> (-12, -5.2)
  line L5 (-9.2, 5.2) -> (-12, 5.2)
  line L6 (-9.2, -5.2) -> (-9.2, 5.2)
  line L7 (-12, 5.2) -> (-9.2, -5.2)
  line L8 (-9.2, 5.2) -> (-12, -5.2)
  point P11 (-10.6, 0)
  point P12 (-10.6, 0)
  horizontal L3
  perpendicular L3 L4
  parallel L3 L5
  parallel L4 L6
  coincident L7 P11
  coincident L8 P11
  coincident P11 P12
extrude "Extrude19" cut sketch "Sketch28" profile of K1 L1 K2 K3 L2 L3 L4 L5 L6 along normal blind 1.6
fillet "Fillet11" radius 1
component_from_bodies "Body->Comp2"
sketch "Springload path" plane through (0, 0, 0) normal (0, 0, 1) x axis (1, 0, 0)
  line L1 (33.1, 4.8) -> (4.3, 15.3)
  line L2 (-64.3321, 10.05) -> (18.7, 10.05)
  circle C1 centre (4.3, 15.3) radius 1.25
  circle C2 centre (4.3, 15.3) radius 2
  point P2 (4.3, 15.3)
  point P4 (4.3, 15.3)
  point P3 (33.1, 4.8)
  point P5 (33.1, 4.8)
  point P6 (18.7, 10.05)
  coincident P2 P4
  coincident P3 P5
  midpoint L1 P6
  horizontal L2
  concentric C1 C2
sketch "SpringloadCenter" plane through (-2, 0, 0) normal (-1, 0, 0) x axis (0, -1, 0)
  line L1 (2, -10.5) -> (-22, -10.5)
  line L2 (2, 10.5) -> (2, -10.5)
  line L3 (-22, 10.5) -> (2, 10.5)
  line L4 (-22, -10.5) -> (-22, 10.5)
  line L5 (-10.05, -6) -> (-10.05, 0)
  line L6 (-14.95, -8) -> (-17.85, -8)
  circle C1 centre (-8.5396, 0) radius 3
  circle C2 centre (-10.05, -6) radius 2.5
  point P7 (-10.05, 0)
  point P9 (-10.05, 0)
  point P8 (-10.05, -6)
  point P12 (-10.05, -6)
  vertical L5
  coincident P7 P9
  coincident P8 P12
  dimension "d207" distance P8 L6 = 2
  dimension "d208" diameter C2 = 5
extrude "Extrude1" cut sketch "SpringloadCenter" profile of C2 to an object
work_plane "WorkPlane6" AlongDistance -41.85
sketch "Sketch32" plane through (39.85, 10, 0) normal (-1, 0, 0) x axis (0, 1, 0)
  circle C1 centre (0.05, 6) radius 2.5
  circle C2 centre (0.05, 6) radius 3.5
  concentric C1 C2
  dimension "d216" diameter C2 = 7
extrude "Extrude2" cut sketch "Sketch32" distance 8
chamfer "Chamfer1" distance 1
fillet "Fillet1" radius 1
thread "Thread1" ThreadOffset 0 ThreadLength 20
work_plane "WorkPlane7" AlongDistance -6
sketch "SpringPinLever" plane through (0, 0, -6) normal (0, 0, 1) x axis (1, 0, 0)
  line L1 (42.85, 10.05) -> (-2, 10.05)
  line L2 (33.85, 8.05) -> (30.3859, 10.05)
  line L3 (33.85, 7.05) -> (33.85, 8.05)
  line L4 (42.85, 7.05) -> (33.85, 7.05)
  line L5 (42.85, 10.05) -> (42.85, 7.05)
  line L6 (27.85, 7.05) -> (33.85, 7.05)
  line L7 (27.85, 10.05) -> (27.85, 7.05)
  line L8 (39.85, 3.1563) -> (39.85, 15.8)
  line L9 (42.85, 10.05) -> (39.85, 7.05)
  circle C1 centre (39.85, 15.8) radius 1.5
  point P2 (-2, 10.05)
  point P3 (-2, 10.05)
  point P4 (30.3859, 10.05)
  point P10 (27.85, 10.05)
  point P11 (39.85, 15.8)
  point P12 (39.85, 15.8)
  point P14 (39.85, 7.05)
  point P15 (42.85, 10.05)
  point P5 (33.85, 8.05)
  coincident P2 P3
  horizontal L1
  coincident L1 P4
  perpendicular L1 L3
  perpendicular L3 L4
  perpendicular L4 L5
  perpendicular L3 L6
  coincident L1 P10
  perpendicular L1 L7
  coincident P11 P12
  perpendicular L4 L8
  coincident L4 P14
  coincident L8 P14
  coincident L5 P15
  dimension "d223" distance L1 L4 = 3
  dimension "d224" angle L1 L2 = 30
  dimension "d225" distance L1 P5 = 2
  dimension "d226" distance L3 L7 = 6
  dimension "d227" distance L3 L8 = 6
  dimension "d228" angle L4 L9 = 45
  dimension "d229" distance L5 L8 = 3
revolve "Revolve1" sketch "SpringPinLever" AlongAngle 360
revolve "Revolve2" sketch "SpringPinLever" AlongAngle 360
sketch "Sketch34" plane through (0, 0, -8) normal (0, 0, -1) x axis (1, 0, 0)
  curve K1 (40.6881, -10.8707) -> (40.6563, -9.1487)
  line L1 (34.1166, -12.2861) -> (36.293, -12.2861)
  line L2 (30.0035, -23.8065) -> (29.665, -17.1005)
  line L3 (40.2281, -23.2905) -> (30.0035, -23.8065)
  line L4 (42.2008, -23.1909) -> (40.2281, -23.2905)
  line L5 (44.8204, -20.2928) -> (42.2008, -23.1909)
  line L6 (48, -3.2852) -> (30.2444, -3.2852)
  line L7 (48, -26) -> (48, -3.2852)
  line L8 (30.2444, -26) -> (48, -26)
  line L9 (30.2444, -3.2852) -> (30.2444, -26)
  arc A1 centre (39.85, -15.8) radius 5 clockwise from (40.6881, -10.8707) to (36.293, -12.2861)
  arc A2 centre (29.5899, -8.66) radius 5.8 clockwise from (34.1166, -12.2861) to (31.987, -13.9414)
  arc A3 centre (33.103, -16.4) radius 2.7 clockwise from (30.5636, -15.4825) to (31.987, -13.9414)
  arc A4 centre (25.1088, -13.5115) radius 5.8 clockwise from (30.5636, -15.4825) to (29.665, -17.1005)
  arc A5 centre (39.85, -15.8) radius 6.7 clockwise from (40.6563, -9.1487) to (44.8204, -20.2928)
  circle C1 centre (33.1, -16.4) radius 1.45
  horizontal L6
  vertical L7
  horizontal L8
  vertical L9
extrude "Extrude1" cut sketch "Sketch34" profile of K1 A1 L1 A2 A3 A4 L3 L4 L5 A5 L6 L7 L8 L9 along normal blind 8.5
sketch "Sketch35" plane through (0, 0, -4) normal (0, 0, -1) x axis (1, 0, 0)
  curve K1 (39.85, -12.2861) -> (40.6881, -10.8707)
  line L1 (36.293, -12.2861) -> (39.85, -12.2861)
  arc A1 centre (39.85, -15.8) radius 5 clockwise from (40.6881, -10.8707) to (36.293, -12.2861)
  circle C1 centre (39.85, -15.8) radius 3
  circle C2 centre (39.85, -15.8) radius 5
  concentric A1 C2
extrude "Extrude2" cut sketch "Sketch35" along normal blind 20
fillet "Fillet1" radius 2
chamfer "Chamfer1" distance 0.5
chamfer "Chamfer2" distance 0.5
chamfer "Chamfer2" distance 6
split "Split1"
sketch "495 cutout" plane through (0, 0, 0) normal (0, 0, 1) x axis (1, 0, 0)
  line L1 (14.26, 17.81) -> (14.26, 16.71)
  line L2 (14.26, 16.71) -> (14.76, 16.21)
  line L3 (14.76, 16.21) -> (18.26, 16.21)
  line L4 (18.26, 16.21) -> (18.76, 16.71)
  line L5 (18.76, 16.71) -> (18.76, 17.81)
  line L6 (13.557, 19.0276) -> (14.26, 17.81)
  line L7 (18.76, 17.81) -> (19.2983, 18.7423)
  line L8 (23.3153, 25.7) -> (19.2983, 18.7423)
  line L9 (9.7047, 25.7) -> (23.3153, 25.7)
  line L10 (13.557, 19.0276) -> (9.7047, 25.7)
  line L11 (18.51, 16.46) -> (14.51, 16.46)
  point P9 (19.2983, 18.7423)
  point P10 (19.2983, 18.7423)
  point P8 (13.557, 19.0276)
  point P13 (13.557, 19.0276)
  point P14 (14.51, 16.46)
  point P15 (18.51, 16.46)
  coincident P9 P10
  parallel L3 L9
  coincident P8 P13
  collinear L7 L8
  collinear L6 L10
  midpoint L2 P14
  midpoint L4 P15
extrude "Extrude3" cut sketch "495 cutout" profile of L1 L2 L3 L4 L5 L6 L7 L8 L9 L10 distance 1.8
extrude "Extrude4" cut sketch "495 cutout" profile of L1 L2 L4 L5 L6 L7 L8 L9 L10 L11 along normal blind 15.5
offset_faces "OffsetFaces1" distance -7
offset_faces "OffsetFaces2" distance -7
fillet "Fillet2" radius 10
fillet "Fillet3" radius 10
sketch "Mounting holes" plane through (0, -2, 0) normal (0, -1, 0) x axis (1, 0, 0)
  line L1 (-2, 0) -> (24.6, 0)
  line L2 (-2, -8.5) -> (-2, 0)
  line L3 (48, -12.5) -> (2, -12.5)
  line L4 (52, 0) -> (52, -8.5)
  line L5 (41.6, 0) -> (52, 0)
  line L6 (41.6, -3.2929) -> (41.6, 0)
  line L7 (25.3071, -4) -> (40.8929, -4)
  line L8 (24.6, 0) -> (24.6, -3.2929)
  line L9 (47.5, 8) -> (2.5, 8)
  line L10 (47.5, -8) -> (47.5, 8)
  line L11 (2.5, -8) -> (47.5, -8)
  line L12 (2.5, 8) -> (2.5, -8)
  line L13 (52, 10.5) -> (52, -10.5)
  line L14 (52, -10.5) -> (-2, 10.5)
  line L15 (47.5, 8) -> (2.5, -8)
  line L16 (25.9586, 9) -> (25.9586, -9)
  circle C1 centre (49, -9.5) radius 1.4
  circle C2 centre (1, -9.5) radius 1.4
  arc A1 centre (2, -8.5) radius 4 clockwise from (2, -12.5) to (-2, -8.5)
  arc A2 centre (48, -8.5) radius 4 clockwise from (52, -8.5) to (48, -12.5)
  closed curve K1 centre (40.1858, -2.5858)
  closed curve K2 centre (26.0142, -2.5858)
  circle C3 centre (1, 9.5) radius 1.4
  point P25 (-2, 10.5)
  point P28 (-2, 10.5)
  point P29 (25, 0)
  point P30 (25, 0)
  point P26 (52, -10.5)
  point P33 (52, -10.5)
  point P21 (2.5, -8)
  point P23 (2.5, 8)
  point P20 (47.5, 8)
  horizontal L9
  vertical L10
  horizontal L11
  vertical L12
  coincident P25 P28
  midpoint L15 P29
  coincident L14 P30
  coincident P26 P33
  midpoint L14 P30
  coincident P29 P30
  dimension "d284" distance P21 P23 = 16
  dimension "d285" distance P20 P23 = 45
hole "Hole1" HoleDepth 6 HoleDiameter 3.7 (= "M3InsertDia") TipAngle 118 CSDiameter 4 CSAngle 90
chamfer "Chamfer3" distance 2
sketch "SpringPlunger" plane through (0, 0, -6) normal (0, 0, 1) x axis (1, 0, 0)
  line L1 (59.8061, 10.05) -> (-2, 10.05)
  line L2 (18.85, 11.55) -> (21.4481, 10.05)
  line L3 (18.85, 12.35) -> (18.85, 11.55)
  line L4 (13.85, 12.35) -> (18.85, 12.35)
  line L5 (13.85, 10.05) -> (13.85, 12.35)
  line L6 (21.4481, 10.05) -> (13.85, 10.05)
  line L7 (33.85, 8.05) -> (33.85, 12.05)
  point P2 (-2, 10.05)
  point P3 (-2, 10.05)
  point P8 (13.85, 12.35)
  point P9 (13.85, 10.05)
  point P6 (18.85, 11.55)
  point P7 (18.85, 12.35)
  coincident P2 P3
  horizontal L1
  perpendicular L1 L3
  perpendicular L3 L4
  perpendicular L4 L5
  perpendicular L5 L6
  coincident P3 L6
  dimension "d257" angle L2 L6 = 30
  dimension "d258" distance P8 P9 = 2.3
  dimension "d259" distance P6 L6 = 1.5
  dimension "d260" distance P7 P8 = 5
  dimension "d261" distance P7 L7 = 15
revolve "Revolve9" sketch "SpringPlunger" AlongAngle 360 bodies "SpringPlunger"
fillet "Fillet12" radius 0.2
base_feature "Base Feature1"
position "Position2"
joint "Assemble3" alignAngle 0 alignOffsetX 0 alignOffsetY 0 alignOffsetZ 0
copy_paste "CutPaste1"
base_feature "Base Feature1"
position "Position3"
joint "Assemble4" alignAngle 180 alignOffsetX 0 alignOffsetY 0 alignOffsetZ 0
copy_paste "CutPaste2"
ground "Ground1"
position "Position4"
joint "Assemble5" alignAngle 0 alignOffsetX 0 alignOffsetY 0 alignOffsetZ 0
component_from_bodies "Body->Comp3"
component_from_bodies "Body->Comp4"
component_from_bodies "Body->Comp5"
component_from_bodies "Body->Comp6"
copy_paste_bodies "CutPasteBodies1"
component_from_bodies "Body->Comp7"
copy_paste_bodies "CutPasteBodies1"
position "Position5"
hole "Hole2" HoleDepth 19 HoleDiameter 2.9 (= "PinPressDia") TipAngle 118 CSDiameter 4 CSAngle 90
sketch "Sketch39" plane through (52, 0, 0) normal (1, 0, 0) x axis (0, 1, 0)
  line L1 (-2, 10.5) -> (22, 10.5)
  line L2 (-2, -10.5) -> (-2, 10.5)
  line L3 (22, -10.5) -> (-2, -10.5)
  line L4 (22, 10.5) -> (22, -10.5)
  line L5 (12.2791, 0.6595) -> (11.4713, 1.4672)
  line L6 (16.4, 0) -> (4.8, 0)
  line L7 (12.2791, 0) -> (12.2791, 0.6595)
  line L8 (11.4, 0) -> (9.8, 0)
  line L9 (12.2791, -0.6595) -> (11.4713, -1.4672)
  line L10 (12.2791, 0) -> (12.2791, -0.6595)
  circle C1 centre (10.0041, 0) radius 7.3589
  circle C2 centre (10.0041, 0) radius 2.075
  point P8 (11.4713, 1.4672)
  point P12 (12.2791, 0)
  point P13 (12.0791, 0)
  point P16 (11.4713, -1.4672)
  point P9 (12.2791, 0.6595)
  point P17 (12.2791, -0.6595)
  point P18 (12.2791, 0)
  concentric C1 C2
  coincident C2 P8
  tangent C2 L5
  coincident L6 P12
  vertical L7
  coincident C2 P13
  coincident L6 P13
  symmetric P8 L6 P16
  symmetric P9 L6 P17
  symmetric L6 P12 P18
  dimension "d290" diameter C2 = 4.15 (= "PTFEclear")
  dimension "d291" distance P12 P13 = 0.2
  dimension "d292" angle L5 L8 = 45
sweep "Sweep1" sketch "Sketch39" TwistAngle 0 TaperAngle 0 bodies "PTFEClearance"
extrude "Extrude20" new body sketch "Sketch12" profile of L1 L2 L3 L4 distance 9
combine "Combine1" bodies "PTFEClearance (1)"
combine "Combine2" bodies "PTFEClearance", "PTFEClearance (1)"
sketch "Sketch40" plane through (0, 0, -12.5) normal (0, 0, -1) x axis (1, 0, 0)
extrude "Extrude5" cut sketch "Sketch40" against normal blind 1
component_insert "Component Insert"
joint "Assemble6" alignAngle 0 alignOffsetX 0 alignOffsetY 0 alignOffsetZ 0
sketch "Sketch41" plane through (0, 0, 12.5) normal (0, 0, 1) x axis (-1, 0, 0)
  line L1 (-20.76, -17.2741) -> (-23.4885, -22)
  line L2 (-20.76, -15.8816) -> (-20.76, -17.2741)
  line L3 (-19.3384, -14.46) -> (-20.76, -15.8816)
  line L4 (-13.6816, -14.46) -> (-19.3384, -14.46)
  line L5 (-12.26, -15.8816) -> (-13.6816, -14.46)
  line L6 (-12.26, -17.2741) -> (-12.26, -15.8816)
  line L7 (-9.5315, -22) -> (-12.26, -17.2741)
  line L8 (0, -22) -> (-9.5315, -22)
  line L9 (0, -17.8515) -> (0, -22)
  line L10 (0, 2) -> (0, -12.7485)
  line L11 (-50, 2) -> (0, 2)
  line L12 (-50, -22) -> (-50, 2)
  line L13 (-23.4885, -22) -> (-50, -22)
  line L14 (-7.345, -1.6) -> (-1.545, -11.1)
  line L15 (-45.72, -3.675) -> (-40.64, -16.375)
  line L16 (-43.93, -1.025) -> (-42.43, -1.025)
  line L17 (-43.93, -19.025) -> (-43.93, -1.025)
  line L18 (-42.43, -19.025) -> (-43.93, -19.025)
  line L19 (-42.43, -1.025) -> (-42.43, -19.025)
  line L20 (-43.93, -19.025) -> (-42.43, -1.025)
  line L21 (-42.43, -19.025) -> (-43.93, -1.025)
  arc A1 centre (-4.3, -15.3) radius 5 clockwise from (0, -17.8515) to (0, -12.7485)
  circle C1 centre (-33.1, -4.8) radius 5
  circle C2 centre (-40.64, -16.375) radius 0.508
  circle C3 centre (-45.72, -3.675) radius 0.508
  circle C4 centre (-4.445, -6.35) radius 2.5
  circle C5 centre (-4.445, -6.35) radius 0.175
  point P18 (-1.545, -11.1)
  point P20 (-1.545, -11.1)
  point P19 (-7.345, -1.6)
  point P21 (-7.345, -1.6)
  point P22 (-40.64, -16.375)
  point P24 (-40.64, -16.375)
  point P23 (-45.72, -3.675)
  point P25 (-45.72, -3.675)
  point P30 (-43.18, -10.025)
  point P28 (-43.93, -19.025)
  point P29 (-42.43, -19.025)
  point P27 (-43.93, -1.025)
  coincident P18 P20
  coincident P19 P21
  coincident P22 P24
  coincident P23 P25
  horizontal L16
  perpendicular L16 L17
  parallel L16 L18
  parallel L17 L19
  coincident L20 P30
  coincident L21 P30
  midpoint L15 P30
  concentric C4 C5
  dimension "d307" distance P28 P29 = 1.5
  dimension "d308" distance P27 P28 = 18
  dimension "d309" diameter C4 = 5
extrude "Extrude6" add sketch "Sketch41" profile of L16 L17 L18 L19 C4 C5 to an object
chamfer "Chamfer4" distance 2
